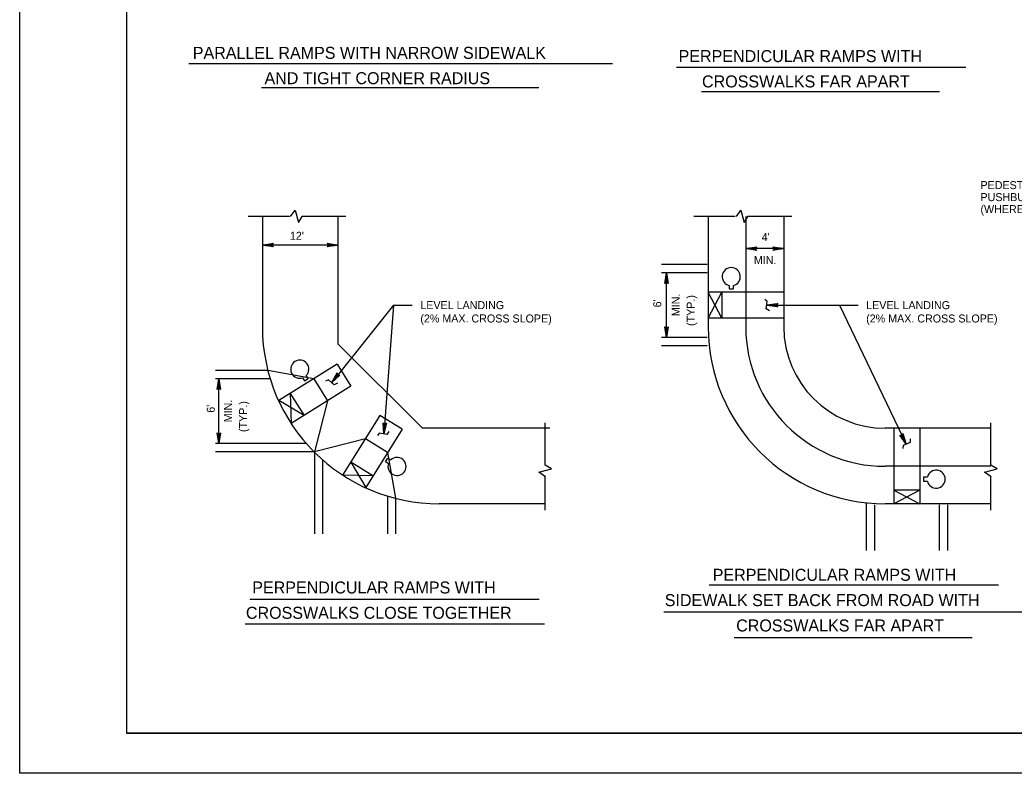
# Model space of a CAD drawing. Extents: x 36 to 940, y -1166 to 1210.
# Drawn here: x 35.9 to 408.6, y -1165.8 to -883.4 of the extents above; entities that cross this region are included whole.
import ezdxf

# ---------------------------------------------------------------- set-up
doc = ezdxf.new("R2010")
doc.units = 0
for name, color, linetype in [('1', 7, 'Continuous'), ('2', 7, 'Continuous'), ('Default', 7, 'Continuous'), ('PLT-BNDY', 7, 'Continuous')]:
    doc.layers.add(name, color=color, linetype=linetype)

msp = doc.modelspace()

# ---------------------------------------------------------------- linework, layer by layer
at = {"layer": '1'}
for p, q in [((75.86, -586.83), (75.86, -1150.83)), ((861.86, -1150.83), (75.86, -1150.83)), ((75.86, -1150.83), (661.86, -1150.83))]:
    msp.add_line(p, q, dxfattribs=at)
at = {"layer": '2'}
for p, q in [((258.09, -899.89), (99.21, -899.89)), ((282.03, -901.12), (390.47, -901.12)), ((230.47, -908.89), (126.42, -908.89)), ((291.44, -910.32), (380.65, -910.32)), ((136.91, -957.16), (121.44, -957.16)), ((126.79, -957.16), (126.79, -998.54)), ((158.07, -957.16), (141.54, -957.16)), ((155.12, -957.16), (155.12, -1004.89)), ((304.07, -957.16), (288.6, -957.16)), ((293.95, -957.16), (293.95, -998.54)), ((308.11, -998.54), (308.11, -957.16)), ((325.23, -957.16), (308.7, -957.16)), ((322.27, -957.16), (322.27, -998.54)), ((155.12, -967.83), (126.79, -967.83)), ((322.27, -969.2), (308.11, -969.2)), ((293.58, -975.16), (276.41, -975.16)), ((293.58, -978.23), (276.41, -978.23)), ((278.29, -1002.54), (278.29, -978.23)), ((301.75, -983), (301.75, -984.3)), ((303.41, -984.3), (303.41, -983)), ((322.27, -985.49), (293.95, -985.49)), ((299.02, -995.28), (293.95, -985.49)), ((293.95, -995.28), (299.02, -985.49)), ((299.02, -985.49), (299.02, -995.28)), ((301.75, -984.3), (303.41, -984.3)), ((175.96, -990.39), (152.83, -1019.38)), ((175.96, -990.39), (172.35, -1038.6)), ((175.96, -990.39), (182.95, -990.39)), ((315.95, -990.39), (350.11, -990.39)), ((343.11, -990.39), (368.11, -1042.49)), ((322.27, -995.28), (293.95, -995.28)), ((293.58, -1002.54), (276.41, -1002.54)), ((155.12, -1004.89), (186.76, -1036.53)), ((293.58, -1005.61), (276.41, -1005.61)), ((154.77, -1012.48), (132.92, -1026.14)), ((154.77, -1012.48), (159.96, -1020.79)), ((128.85, -1014.94), (109.25, -1014.94)), ((146.02, -1017.95), (128.85, -1014.94)), ((141.84, -1017.62), (142.53, -1018.72)), ((143.94, -1017.85), (143.25, -1016.74)), ((129.71, -1018.01), (109.25, -1018.01)), ((110.43, -1042.31), (110.43, -1018.01)), ((159.96, -1020.79), (137.57, -1034.78)), ((142.53, -1018.72), (143.94, -1017.85)), ((146.02, -1017.95), (151.21, -1026.26)), ((137.23, -1023.45), (142.41, -1031.75)), ((137.23, -1023.45), (137.57, -1034.78)), ((142.41, -1031.75), (132.92, -1026.14)), ((151.21, -1026.26), (146.31, -1045.38)), ((170.87, -1031.69), (156.87, -1054.09)), ((179.17, -1036.88), (170.87, -1031.69)), ((232.79, -1050.32), (232.79, -1034.51)), ((399.94, -1050.32), (399.94, -1034.51)), ((179.17, -1036.88), (165.52, -1058.73)), ((234.49, -1036.53), (186.76, -1036.53)), ((399.94, -1036.53), (360.27, -1036.53)), ((363.53, -1036.53), (363.53, -1064.86)), ((373.32, -1036.53), (373.32, -1064.86)), ((143.29, -1042.31), (109.25, -1042.31)), ((165.4, -1040.44), (146.27, -1045.34)), ((173.7, -1045.63), (165.4, -1040.44)), ((146.31, -1045.38), (109.25, -1045.38)), ((146.27, -1045.34), (146.27, -1076.12)), ((173.7, -1045.63), (176.72, -1062.8)), ((149.34, -1048.37), (149.34, -1076.12)), ((168.21, -1054.43), (159.9, -1049.24)), ((159.9, -1049.24), (165.52, -1058.73)), ((172.93, -1049.12), (173.81, -1047.72)), ((174.03, -1049.81), (172.93, -1049.12)), ((173.81, -1047.72), (174.91, -1048.41)), ((399.94, -1050.8), (360.27, -1050.8)), ((168.21, -1054.43), (156.87, -1054.09)), ((232.79, -1067.24), (232.79, -1054.57)), ((374.82, -1056.45), (374.82, -1054.79)), ((374.82, -1054.79), (376.12, -1054.79)), ((399.94, -1067.24), (399.94, -1054.57)), ((376.12, -1056.45), (374.82, -1056.45)), ((173.65, -1061.94), (173.65, -1076.12)), ((373.32, -1059.79), (363.53, -1059.79)), ((363.53, -1059.79), (373.32, -1064.86)), ((373.32, -1059.79), (363.53, -1064.86)), ((176.72, -1062.8), (176.72, -1076.12)), ((232.79, -1064.86), (193.12, -1064.86)), ((353.2, -1064.49), (353.2, -1082.4)), ((356.27, -1065.23), (356.27, -1082.4)), ((399.94, -1064.86), (360.27, -1064.86)), ((380.58, -1065.23), (380.58, -1082.4)), ((383.65, -1065.23), (383.65, -1082.4)), ((294.3, -1095.29), (402.74, -1095.29)), ((122.13, -1100.61), (230.57, -1100.61)), ((277.32, -1105.31), (420.95, -1105.31)), ((120.29, -1109.81), (232.51, -1109.81)), ((303.72, -1114.93), (392.92, -1114.93))]:
    msp.add_line(p, q, dxfattribs=at)
for points in [[(137.34, -957.19), (139.03, -954.71), (140.29, -959.45), (141.65, -957.08)], [(304.5, -957.19), (306.18, -954.71), (307.45, -959.45), (308.8, -957.08)], [(130.65, -968.32), (130.51, -968.04), (126.79, -967.83), (130.65, -968.32), (130.85, -968.48), (126.79, -967.83), (130.5, -967.65), (130.64, -967.37), (126.79, -967.83), (130.85, -967.19), (130.64, -967.37)], [(151.26, -967.35), (151.4, -967.63), (155.12, -967.83), (151.26, -967.35), (151.06, -967.18), (155.12, -967.83), (151.41, -968.01), (151.27, -968.29), (155.12, -967.83), (151.06, -968.48), (151.27, -968.29)], [(311.97, -969.69), (311.83, -969.41), (308.11, -969.2), (311.97, -969.69), (312.17, -969.86), (308.11, -969.2), (311.82, -969.02), (311.96, -968.74), (308.11, -969.2), (312.17, -968.56), (311.96, -968.74)], [(318.42, -968.72), (318.56, -969), (322.27, -969.2), (318.42, -968.72), (318.22, -968.55), (322.27, -969.2), (318.56, -969.39), (318.43, -969.66), (322.27, -969.2), (318.22, -969.85), (318.43, -969.66)], [(277.81, -982.09), (278.09, -981.95), (278.29, -978.23), (277.81, -982.09), (277.64, -982.29), (278.29, -978.23), (278.47, -981.95), (278.75, -982.08), (278.29, -978.23), (278.94, -982.29), (278.75, -982.08)], [(316.94, -992.49), (315.72, -991.8), (316.08, -988.95), (315.14, -988.31)], [(319.81, -990.87), (319.66, -990.59), (315.95, -990.39), (319.81, -990.87), (320, -991.04), (315.95, -990.39), (319.66, -990.2), (319.79, -989.93), (315.95, -990.39), (320, -989.74), (319.79, -989.93)], [(278.78, -998.68), (278.5, -998.83), (278.29, -1002.54), (278.78, -998.68), (278.94, -998.48), (278.29, -1002.54), (278.11, -998.83), (277.83, -998.69), (278.29, -1002.54), (277.65, -998.48), (277.83, -998.69)], [(155.62, -1016.67), (155.31, -1016.6), (152.83, -1019.38), (155.62, -1016.67), (155.87, -1016.62), (152.83, -1019.38), (155, -1016.36), (154.87, -1016.09), (152.83, -1019.38), (154.86, -1015.81), (154.87, -1016.09)], [(109.95, -1021.87), (110.23, -1021.72), (110.43, -1018.01), (109.95, -1021.87), (109.78, -1022.06), (110.43, -1018.01), (110.62, -1021.72), (110.89, -1021.85), (110.43, -1018.01), (111.08, -1022.06), (110.89, -1021.85)], [(154.91, -1019.59), (153.74, -1020.26), (151.53, -1018.43), (150.48, -1018.88)], [(173.12, -1034.78), (172.84, -1034.91), (172.35, -1038.6), (173.12, -1034.78), (173.31, -1034.6), (172.35, -1038.6), (172.45, -1034.88), (172.18, -1034.73), (172.35, -1038.6), (172.01, -1034.5), (172.18, -1034.73)], [(110.92, -1038.45), (110.64, -1038.6), (110.43, -1042.31), (110.92, -1038.45), (111.09, -1038.26), (110.43, -1042.31), (110.25, -1038.6), (109.97, -1038.47), (110.43, -1042.31), (109.79, -1038.26), (109.97, -1038.47)], [(174.13, -1037.72), (173.45, -1038.88), (170.62, -1038.4), (169.94, -1039.31)], [(366.87, -1038.8), (366.68, -1039.05), (368.11, -1042.49), (366.87, -1038.8), (366.94, -1038.55), (368.11, -1042.49), (366.33, -1039.22), (366.03, -1039.22), (368.11, -1042.49), (365.77, -1039.11), (366.03, -1039.22)], [(369.61, -1040.56), (369.66, -1041.91), (367.01, -1043.01), (366.92, -1044.14)], [(232.87, -1054.69), (230.39, -1053), (235.13, -1051.74), (232.76, -1050.38)], [(400.02, -1054.69), (397.54, -1053), (402.28, -1051.74), (399.91, -1050.38)]]:
    msp.add_lwpolyline(points, dxfattribs=at)
for centre, radius, start, end in [((302.58, -979.71), 3.4, 284.1014, 255.8986), ((193.12, -998.54), 66.33, 180, 270), ((360.27, -998.54), 66.33, 180, 270), ((360.27, -998.54), 52.26, 180, 270), ((360.27, -998.54), 38, 180, 270), ((140.8, -1014.39), 3.4, 316.1014, 287.8986), ((177.26, -1050.85), 3.4, 162.1014, 133.8986), ((379.41, -1055.62), 3.4, 194.1014, 165.8986)]:
    msp.add_arc(centre, radius, start, end, dxfattribs=at)
at = {"layer": 'PLT-BNDY'}
msp.add_lwpolyline([(35.86, -571.83), (876.86, -571.83), (876.86, -1165.83), (35.86, -1165.83)], close=True, dxfattribs=at)

# ---------------------------------------------------------------- texts
at = {"layer": '2'}
for s, height, p in [('PARALLEL RAMPS WITH NARROW SIDEWALK', 4.5, (100.68, -898.03)), ('PERPENDICULAR RAMPS WITH', 4.5, (282.82, -899.25)), ('AND TIGHT CORNER RADIUS', 4.5, (127.57, -907.53)), ('CROSSWALKS FAR APART', 4.5, (291.61, -908.75)), ("12'", 3, (137.09, -965.87)), ("4'", 3, (313.97, -966.35)), ('MIN.', 3, (311.05, -975)), ('LEVEL LANDING', 3, (186, -991.88)), ('LEVEL LANDING', 3, (353.16, -991.88)), ('(2% MAX. CROSS SLOPE)', 3, (186, -996.88)), ('(2% MAX. CROSS SLOPE)', 3, (353.16, -996.88)), ('PERPENDICULAR RAMPS WITH', 4.5, (295.64, -1093.73)), ('PERPENDICULAR RAMPS WITH', 4.5, (122.99, -1098.48)), ('SIDEWALK SET BACK FROM ROAD WITH', 4.5, (277.64, -1103.23)), ('CROSSWALKS CLOSE TOGETHER', 4.5, (120.61, -1107.98)), ('CROSSWALKS FAR APART', 4.5, (304.42, -1112.73))]:
    msp.add_text(s, height=height, dxfattribs=at).set_placement(p)
for s, p in [('MIN.', (283.26, -994.52)), ('(TYP.)', (288.9, -998.18)), ("6'", (276.33, -991.21)), ("6'", (108.92, -1030.7)), ('MIN.', (115.4, -1034.29)), ('(TYP.)', (121.04, -1037.95))]:
    msp.add_text(s, height=3, rotation=90, dxfattribs=at).set_placement(p)
at = {"layer": 'Default'}
for s, p in [('PEDESTRIAN', (396.01, -946.87)), ('PUSHBUTTON', (396.01, -951.37)), ('(WHERE APPLICABLE)', (396.01, -955.87))]:
    msp.add_text(s, height=3, dxfattribs=at).set_placement(p)

doc.saveas('drawing.dxf')
